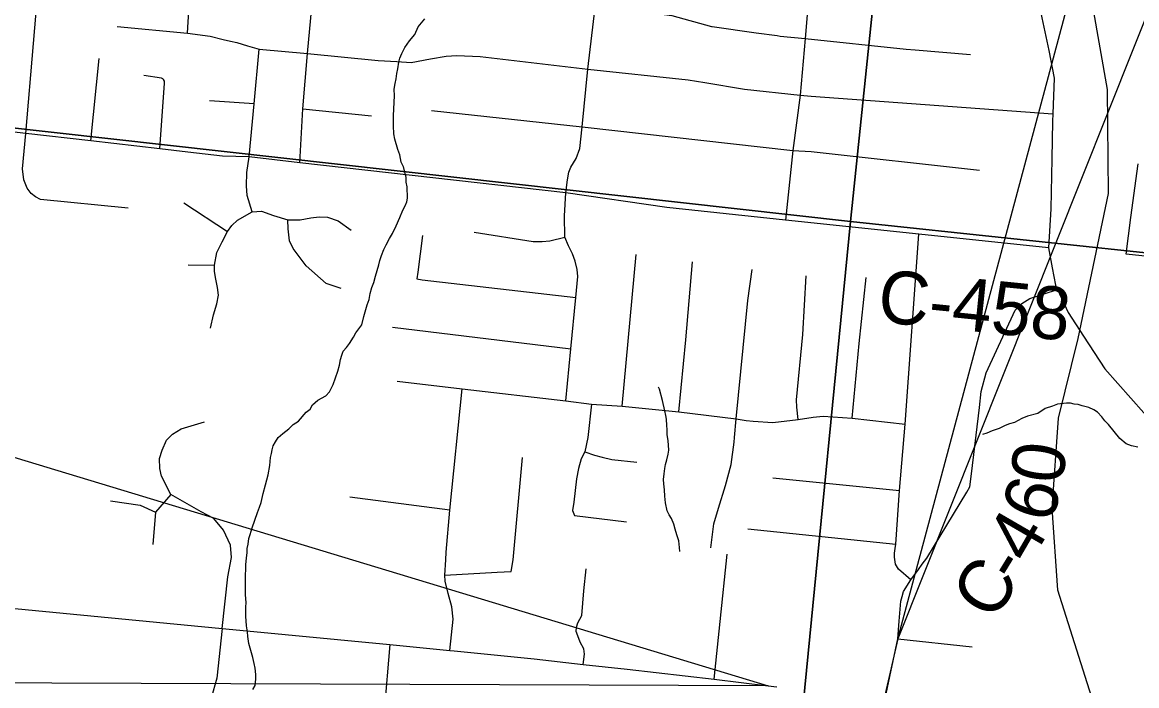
# Model space of a CAD drawing. Extents: x 0 to 43.4, y -8.1 to 22.
# Drawn here: x 6.05 to 7.249, y 18.884 to 19.598 of the extents above; entities that cross this region are included whole.
import ezdxf

# ---------------------------------------------------------------- set-up
doc = ezdxf.new("R2010")
doc.units = 0
for name, color, linetype in [('GM_X_Corporation', 7, 'Continuous'), ('GM_X_County_Road', 7, 'Continuous'), ('GM_X_County_Road_Text', 7, 'Continuous'), ('GM_X_Minor_River', 7, 'Continuous'), ('GM_X_Rail_Line', 7, 'Continuous'), ('GM_X_State_Route', 7, 'Continuous'), ('GM_X_Township_Road', 7, 'Continuous'), ('SH_Text', 7, 'Continuous')]:
    doc.layers.add(name, color=color, linetype=linetype)

msp = doc.modelspace()

# ---------------------------------------------------------------- linework, layer by layer
at = {"layer": 'GM_X_Corporation'}
for points in [[(7.0465, 20.3953), (6.9413, 19.3833), (5.9616, 19.4927), (6.0521, 20.4929)], [(7.0465, 20.3953), (8.0517, 20.2839), (7.955, 19.3167), (7.3077, 19.3879), (7.3067, 19.3445), (6.9413, 19.3833)], [(5.9616, 19.4927), (6.9413, 19.3833), (6.8431, 18.3799), (5.8893, 18.4791)], [(7.955, 19.3167), (7.9506, 19.2736), (7.8526, 18.2674), (6.8431, 18.3799), (6.9413, 19.3833), (7.3067, 19.3445), (7.3077, 19.3879)]]:
    msp.add_lwpolyline(points, close=True, dxfattribs=at)
msp.add_lwpolyline([(7.2817, 19.3433), (7.2379, 19.348), (7.2432, 19.3876), (7.2511, 19.4455)], dxfattribs=at)
at = {"layer": 'GM_X_County_Road'}
msp.add_line((5.9863, 18.9721), (6.2648, 18.9452), dxfattribs=at)
for points in [[(7.1544, 19.3549), (7.0147, 19.3696), (6.8713, 19.3847), (6.7437, 19.3982), (6.635, 19.4142), (6.3486, 19.4465), (6.2939, 19.453), (6.2651, 19.4537), (6.2278, 19.458), (6.1978, 19.4615), (6.1234, 19.47), (6.0534, 19.478), (5.9566, 19.4892)], [(7.0186, 19.0144), (7.0233, 19.021), (7.0666, 19.0919), (7.0698, 19.0975), (7.0714, 19.1115), (7.0802, 19.183), (7.0819, 19.2004), (7.0875, 19.2204), (7.1075, 19.2638), (7.1185, 19.2877), (7.1256, 19.2951), (7.1345, 19.3005), (7.1641, 19.3099)], [(6.9936, 18.9529), (6.9954, 18.9746), (6.9969, 18.9796), (6.9985, 18.9849), (7.0064, 18.9976), (7.0145, 19.0085), (7.0186, 19.0144)], [(6.2648, 18.9452), (6.2762, 18.9441), (6.4455, 18.9278), (6.51, 18.9216), (6.5147, 18.9212), (6.6008, 18.9124), (6.6536, 18.9063), (6.701, 18.9015), (6.7946, 18.8905), (6.8528, 18.8836), (6.8619, 18.8825)], [(6.9786, 18.8698), (6.9921, 18.9339), (6.9936, 18.9529)]]:
    msp.add_lwpolyline(points, dxfattribs=at)
at = {"layer": 'GM_X_Minor_River'}
for points in [[(6.3068, 19.0809), (6.3091, 19.0904), (6.3117, 19.0998), (6.3143, 19.1107), (6.3162, 19.1205), (6.3169, 19.1293), (6.3181, 19.1334), (6.3187, 19.1376), (6.3199, 19.1417), (6.3224, 19.1462), (6.3252, 19.1506), (6.3303, 19.155), (6.3365, 19.1601), (6.3413, 19.1649), (6.3471, 19.1685), (6.3554, 19.1781), (6.3597, 19.1814), (6.3621, 19.1858), (6.368, 19.191), (6.3765, 19.1956), (6.3804, 19.2), (6.3845, 19.2079), (6.3895, 19.2221), (6.3913, 19.2285), (6.3923, 19.2346), (6.3936, 19.2395), (6.3952, 19.2436), (6.3988, 19.2477), (6.402, 19.2521), (6.4064, 19.2588), (6.4088, 19.2633), (6.4152, 19.2722), (6.4174, 19.2809), (6.4209, 19.2937), (6.423, 19.2993), (6.4243, 19.3057), (6.4261, 19.3121), (6.4282, 19.3177), (6.4299, 19.3245), (6.4334, 19.3366), (6.4347, 19.3411), (6.4364, 19.3467), (6.4389, 19.3531), (6.4413, 19.3583), (6.445, 19.365), (6.4482, 19.3702), (6.4523, 19.3785), (6.456, 19.3875), (6.4593, 19.3953), (6.4618, 19.4002), (6.4638, 19.4043), (6.4643, 19.4085), (6.464, 19.4206), (6.463, 19.4256), (6.4628, 19.4309), (6.4602, 19.4421), (6.4577, 19.4471), (6.4561, 19.4551), (6.454, 19.4609), (6.4506, 19.472), (6.4496, 19.4778), (6.4495, 19.4861), (6.4495, 19.4972), (6.4503, 19.5184), (6.4502, 19.5256), (6.4511, 19.5317), (6.4521, 19.537), (6.453, 19.5426), (6.4539, 19.5476), (6.455, 19.5547), (6.4562, 19.5589), (6.4583, 19.5641), (6.4616, 19.5705), (6.4664, 19.5779), (6.4723, 19.5846), (6.476, 19.5928), (6.4831, 19.6013)], [(6.7577, 19.0279), (6.7573, 19.0323), (6.7564, 19.0395), (6.7544, 19.0461), (6.7527, 19.0522), (6.751, 19.0576), (6.7485, 19.0634), (6.746, 19.0676), (6.7439, 19.0719), (6.7423, 19.0803), (6.7414, 19.0876), (6.7409, 19.0944), (6.7403, 19.1009), (6.7401, 19.1055), (6.7407, 19.1115), (6.7413, 19.1172), (6.7422, 19.1217), (6.7435, 19.1266), (6.7449, 19.1327), (6.7458, 19.1372), (6.745, 19.1475), (6.7441, 19.1536), (6.7439, 19.1593), (6.7436, 19.1635), (6.7431, 19.1704), (6.7425, 19.1746), (6.7415, 19.1795), (6.7389, 19.1907), (6.7355, 19.2026), (6.7347, 19.2051)], [(7.2505, 19.1403), (7.2437, 19.1416), (7.2381, 19.1441), (7.2314, 19.1497), (7.2252, 19.1571), (7.219, 19.1649), (7.215, 19.1688), (7.2117, 19.1731), (7.2073, 19.1779), (7.2033, 19.1807), (7.198, 19.1831), (7.1905, 19.1849), (7.1864, 19.1862), (7.1822, 19.1867), (7.1781, 19.1876), (7.1739, 19.1878), (7.164, 19.1866), (7.1586, 19.1845), (7.1509, 19.1821), (7.1431, 19.1767), (7.132, 19.1736), (7.1259, 19.1712), (7.1177, 19.1669), (7.1124, 19.1656), (7.1078, 19.1638), (7.1012, 19.1606), (7.0939, 19.1578), (7.0881, 19.1554), (7.0835, 19.154)], [(6.298, 18.8794), (6.3004, 18.8839), (6.301, 18.8907), (6.3012, 18.8956), (6.3003, 18.9025), (6.2993, 18.9075), (6.298, 18.914), (6.2936, 18.929), (6.2924, 18.9366), (6.2922, 18.9416), (6.2912, 18.9481), (6.2905, 18.9584), (6.2904, 18.9682), (6.2906, 18.9732), (6.2901, 18.9812), (6.2899, 18.9861), (6.29, 18.9903), (6.2899, 18.9975), (6.2905, 19.0139), (6.2911, 19.0207), (6.2917, 19.0271), (6.2918, 19.0313), (6.2928, 19.0358), (6.2937, 19.0419), (6.295, 19.0464), (6.2972, 19.0535), (6.303, 19.0701), (6.3051, 19.0757), (6.3068, 19.0809)]]:
    msp.add_lwpolyline(points, dxfattribs=at)
at = {"layer": 'GM_X_Rail_Line'}
msp.add_lwpolyline([(7.2632, 18.7074), (7.2074, 18.8505), (7.1644, 18.9863), (7.1583, 19.0746), (7.1652, 19.1715), (7.1865, 19.2573), (7.219, 19.4133), (7.2179, 19.5252), (7.2022, 19.6149), (7.1807, 19.6909), (7.1291, 19.7994), (7.0756, 19.9038), (7.0435, 19.9755), (6.9966, 20.0582), (6.9615, 20.1077), (6.8485, 20.2259), (6.7559, 20.3339), (6.7119, 20.4011), (6.6759, 20.48), (6.6457, 20.5375), (6.5931, 20.6104)], dxfattribs=at)
at = {"layer": 'GM_X_State_Route'}
for points in [[(7.0602, 19.9389), (7.0616, 19.9231), (7.0631, 19.8875), (7.0657, 19.8662), (7.0718, 19.849), (7.0763, 19.8363), (7.0936, 19.7983), (7.1124, 19.7595), (7.1163, 19.7484), (7.1361, 19.6557), (7.1474, 19.6024), (7.1549, 19.5672), (7.1606, 19.5374), (7.1591, 19.4991), (7.1588, 19.4911), (7.158, 19.4508)], [(7.158, 19.4508), (7.1569, 19.397), (7.1544, 19.3549), (7.1585, 19.3335), (7.1618, 19.3148), (7.1641, 19.3099), (7.1755, 19.2853), (7.1921, 19.2599)], [(7.1921, 19.2599), (7.2151, 19.2247), (7.2989, 19.1298), (7.3173, 19.1096)]]:
    msp.add_lwpolyline(points, dxfattribs=at)
at = {"layer": 'GM_X_Township_Road'}
for p, q in [((6.1234, 19.47), (6.1325, 19.5587)), ((6.2994, 19.5099), (6.2512, 19.5131)), ((6.3519, 19.5047), (6.4255, 19.4969)), ((6.2238, 19.4034), (6.2705, 19.3725)), ((6.6955, 19.1845), (6.7104, 19.3478)), ((6.2282, 19.3365), (6.2565, 19.3361)), ((6.4483, 19.2694), (6.6401, 19.2463)), ((6.8578, 19.1073), (6.9939, 19.0937)), ((6.5099, 19.0725), (6.4022, 19.0866)), ((6.8307, 19.0524), (6.9902, 19.036)), ((6.9921, 18.9339), (7.0723, 18.9254))]:
    msp.add_line(p, q, dxfattribs=at)
for points in [[(6.3486, 19.4465), (6.3519, 19.5047), (6.3566, 19.564), (6.3625, 19.6258), (6.3673, 19.6875), (6.3684, 19.7015), (6.3686, 19.7094), (6.3654, 19.7163), (6.3579, 19.731), (6.3531, 19.7389), (6.3512, 19.7462), (6.3648, 19.9527), (6.3775, 20.117)], [(6.2277, 19.5861), (6.2305, 19.6346), (6.2368, 19.6973)], [(6.1638, 19.3976), (6.0692, 19.4069), (6.064, 19.4097), (6.0591, 19.4133), (6.0548, 19.4192), (6.0513, 19.428), (6.0501, 19.4398), (6.0534, 19.478), (6.0699, 19.672)], [(6.6347, 19.1902), (6.6401, 19.2463), (6.6456, 19.3013), (6.6478, 19.324), (6.6471, 19.3316), (6.6449, 19.3406), (6.642, 19.3486), (6.6378, 19.3572), (6.6339, 19.3663), (6.6334, 19.3893), (6.635, 19.4142), (6.6368, 19.4282), (6.6382, 19.4362), (6.6403, 19.4417), (6.6461, 19.451), (6.6498, 19.4619), (6.6523, 19.4851), (6.6587, 19.5473), (6.6682, 19.629)], [(6.6386, 19.6323), (6.6682, 19.629), (6.6753, 19.6283), (6.6852, 19.6262), (6.6923, 19.6236), (6.7011, 19.6183), (6.7089, 19.6134), (6.7241, 19.6081), (6.7491, 19.605), (6.7915, 19.5931), (6.7925, 19.593)], [(6.897, 19.6288), (6.8948, 19.6056), (6.8924, 19.5804), (6.887, 19.5194), (6.8793, 19.4597), (6.8713, 19.3847)], [(6.1518, 19.593), (6.2277, 19.5861), (6.2521, 19.5826), (6.266, 19.5791), (6.2738, 19.5774), (6.2807, 19.5759), (6.2922, 19.5724), (6.3048, 19.5689), (6.3566, 19.564), (6.4327, 19.5567), (6.4529, 19.5555), (6.4683, 19.5544), (6.489, 19.5584), (6.5062, 19.5612), (6.5176, 19.5618), (6.5426, 19.5609), (6.6587, 19.5473), (6.7664, 19.5357), (6.7843, 19.5328), (6.8271, 19.5258), (6.887, 19.5194), (6.8989, 19.5181), (7.1591, 19.4991)], [(6.7925, 19.593), (6.8398, 19.5864), (6.8625, 19.5833)], [(6.8625, 19.5833), (6.8655, 19.5829), (6.8924, 19.5804), (7.0011, 19.5689)], [(6.2939, 19.453), (6.2994, 19.5099), (6.3048, 19.5689)], [(7.0011, 19.5689), (7.011, 19.5679), (7.0706, 19.563)], [(6.1978, 19.4615), (6.2029, 19.5322), (6.2027, 19.5344), (6.2019, 19.536), (6.201, 19.5369), (6.1997, 19.5376), (6.1804, 19.5405)], [(6.4903, 19.5028), (6.6523, 19.4851), (6.8793, 19.4597), (6.899, 19.4586), (7.0802, 19.4386)], [(6.2972, 19.3936), (6.2918, 19.4112), (6.291, 19.4216), (6.2916, 19.436), (6.2939, 19.453)], [(6.2523, 19.2683), (6.2556, 19.2827), (6.259, 19.2947), (6.2608, 19.3041), (6.26, 19.3122), (6.2579, 19.3212), (6.2567, 19.3294), (6.2565, 19.3361), (6.2591, 19.3499), (6.2648, 19.3615), (6.2705, 19.3725), (6.2753, 19.3789), (6.2815, 19.3848), (6.2972, 19.3936), (6.3071, 19.3944), (6.3202, 19.3898), (6.3357, 19.385), (6.3489, 19.3852), (6.3604, 19.3873), (6.3694, 19.3884), (6.3784, 19.3879), (6.3896, 19.3838), (6.4037, 19.3741)], [(6.393, 19.311), (6.3769, 19.3166), (6.3552, 19.3355), (6.3412, 19.3543), (6.3372, 19.3626), (6.3361, 19.3754), (6.3357, 19.385)], [(6.4805, 19.3681), (6.4757, 19.3288), (6.4743, 19.3214), (6.4802, 19.3204), (6.6456, 19.3013)], [(6.5362, 19.3718), (6.5998, 19.3619), (6.6094, 19.3616), (6.6178, 19.3626), (6.6339, 19.3663)], [(7.0064, 18.9976), (6.9928, 19.0089), (6.9897, 19.0145), (6.9886, 19.022), (6.9888, 19.0263), (6.9892, 19.0311), (6.9902, 19.036), (6.9939, 19.0937), (7.0003, 19.1651), (7.0147, 19.3696)], [(6.7564, 19.1783), (6.7639, 19.2558), (6.7712, 19.3399)], [(6.8165, 19.1508), (6.8183, 19.171), (6.8308, 19.2983), (6.8354, 19.3316)], [(6.885, 19.1701), (6.8835, 19.1835), (6.8832, 19.1913), (6.8901, 19.2617), (6.8936, 19.3247)], [(6.943, 19.1717), (6.9507, 19.2519), (6.9582, 19.3229)], [(6.4534, 19.2115), (6.5231, 19.203), (6.6347, 19.1902), (6.6625, 19.1865), (6.6955, 19.1845), (6.7564, 19.1783), (6.8183, 19.171), (6.8291, 19.169), (6.8365, 19.1682), (6.8578, 19.1668), (6.885, 19.1701), (6.9011, 19.1728), (6.9118, 19.1738), (6.943, 19.1717), (7.0003, 19.1651)], [(6.51, 18.9216), (6.5136, 18.9553), (6.5121, 18.9685), (6.5082, 18.9827), (6.5049, 18.9962), (6.5045, 19.0027), (6.5058, 19.0192), (6.5062, 19.0274), (6.5099, 19.0725), (6.5231, 19.203)], [(6.6625, 19.1865), (6.6584, 19.1506), (6.6552, 19.1352), (6.6514, 19.1278), (6.6486, 19.1174), (6.6465, 19.1063), (6.6436, 19.081), (6.6422, 19.072), (6.644, 19.0666), (6.7001, 19.0599)], [(6.2648, 18.9452), (6.2709, 19.0006), (6.2749, 19.0217), (6.2737, 19.0348), (6.2665, 19.051), (6.2559, 19.0636), (6.2422, 19.0709), (6.2098, 19.0895), (6.1995, 19.109), (6.1979, 19.1175), (6.1974, 19.1282), (6.2002, 19.1371), (6.2049, 19.1477), (6.2113, 19.1545), (6.2206, 19.1602), (6.2459, 19.1675)], [(6.7911, 19.0319), (6.7941, 19.0579), (6.7993, 19.0745), (6.8068, 19.0989), (6.8128, 19.1216), (6.816, 19.1457), (6.8165, 19.1508)], [(6.6552, 19.1352), (6.6658, 19.1316), (6.6738, 19.1294), (6.6845, 19.127), (6.7113, 19.1242)], [(6.5045, 19.0027), (6.5611, 19.0058), (6.5761, 19.0064), (6.5782, 19.0191), (6.5882, 19.1291)], [(6.2098, 19.0895), (6.1931, 19.0704), (6.1904, 19.0355)], [(6.1445, 19.0824), (6.1767, 19.0778), (6.1931, 19.0704)], [(6.7946, 18.8905), (6.801, 18.9526), (6.8084, 19.0252)], [(6.6536, 18.9063), (6.655, 18.9175), (6.6542, 18.9232), (6.6504, 18.9306), (6.6478, 18.9371), (6.6461, 18.942), (6.6464, 18.9467), (6.6478, 18.9513), (6.6519, 18.9593), (6.6544, 18.9856), (6.6567, 19.0093)], [(6.2648, 18.9452), (6.2592, 18.8915), (6.2531, 18.8703), (6.2445, 18.8518), (6.2283, 18.8308), (6.2124, 18.8132), (6.1976, 18.8034), (6.1795, 18.7969), (6.1609, 18.7918), (6.1494, 18.7878), (6.1379, 18.7852), (6.104, 18.7882)], [(6.4455, 18.9278), (6.4332, 18.7844), (6.4192, 18.7199)]]:
    msp.add_lwpolyline(points, dxfattribs=at)
at = {"layer": 'SH_Text'}
for points in [[(7.4161, 19.9964), (6.9921, 18.9339), (7.4161, 20.5159)], [(5.117, 19.4094), (6.8528, 18.8836), (5.117, 18.89)]]:
    msp.add_lwpolyline(points, close=True, dxfattribs=at)
msp.add_lwpolyline([(6.9921, 18.9339), (6.9776, 18.8701), (6.9727, 18.8404), (6.9134, 18.7404)], dxfattribs=at)

# ---------------------------------------------------------------- texts
at = {"layer": 'GM_X_County_Road_Text'}
for s, height, rotation, p in [('C-458', 0.05682, 354.2285, (6.9691, 19.2755)), ('0', 0.0568, 82.174, (7.1691, 19.0994)), ('6', 0.0568, 73.6665, (7.1574, 19.0568)), ('4', 0.0568, 59.904, (7.134, 19.0129)), ('C', 0.0568, 57.3281, (7.0951, 18.9513)), ('-', 0.0568, 58.4922, (7.121, 18.9916))]:
    msp.add_text(s, height=height, rotation=rotation, dxfattribs=at).set_placement(p)

doc.saveas('drawing.dxf')
